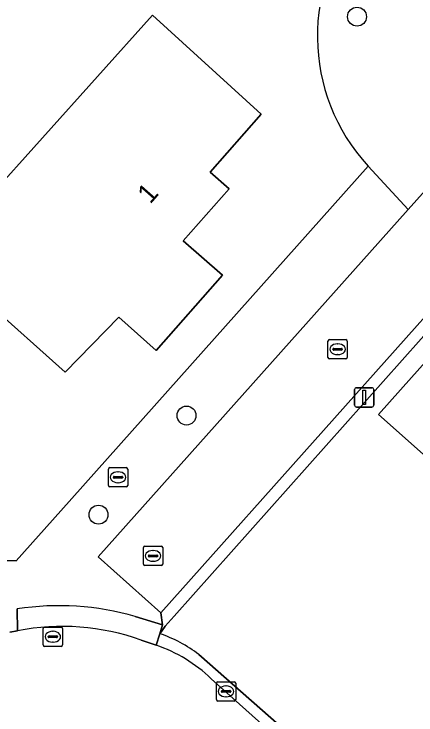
# Model space of a CAD drawing. Extents: x 157648 to 158502, y 379212 to 380938.
# Drawn here: x 158375.88 to 158396.67, y 380278.71 to 380314.96 of the extents above; entities that cross this region are included whole.
import ezdxf

# ---------------------------------------------------------------- set-up
doc = ezdxf.new("R2010")
doc.units = 0
for name, color, linetype in [('IMGEO_Boom', 7, 'Continuous'), ('IMGEO_Brandkraan', 7, 'Continuous'), ('IMGEO_Erf', 7, 'Continuous'), ('IMGEO_Kolk', 7, 'Continuous'), ('IMGEO_Lichtmast', 7, 'Continuous'), ('IMGEO_Pand', 7, 'Continuous'), ('IMGEO_Pand_nummerreeks', 7, 'Continuous'), ('IMGEO_Rijbaan_lokaal_open', 7, 'Continuous'), ('IMGEO_Rioolput', 7, 'Continuous'), ('IMGEO_Voetpad_open', 7, 'Continuous')]:
    doc.layers.add(name, color=color, linetype=linetype)

msp = doc.modelspace()

# ---------------------------------------------------------------- linework, layer by layer
at = {"layer": 'IMGEO_Boom'}
for centre in [(158393.623, 380314.818), (158384.804, 380294.193), (158380.252, 380289.068)]:
    msp.add_circle(centre, 0.489, dxfattribs=at)
at = {"layer": 'IMGEO_Brandkraan'}
for p, q in [((158380.763, 380290.577), (158380.763, 380291.429)), ((158380.838, 380291.503), (158381.69, 380291.503)), ((158381.251, 380291.283), (158381.276, 380291.283)), ((158381.764, 380291.429), (158381.764, 380290.577)), ((158381.022, 380290.997), (158381.022, 380291.009)), ((158381.46, 380290.96), (158381.062, 380290.96)), ((158381.065, 380291.046), (158381.463, 380291.046)), ((158381.506, 380291.009), (158381.506, 380290.997)), ((158381.69, 380290.503), (158380.838, 380290.503)), ((158381.274, 380290.723), (158381.249, 380290.723))]:
    msp.add_line(p, q, dxfattribs=at)
for points in [[(158380.763, 380290.577), (158380.763, 380291.429)], [(158380.838, 380291.503), (158381.69, 380291.503)], [(158381.764, 380291.429), (158381.764, 380290.577)], [(158381.69, 380290.503), (158380.838, 380290.503)]]:
    msp.add_lwpolyline(points, dxfattribs=at)
for centre, radius, start, end in [((158380.84, 380291.427), 0.0765, 91.552, 178.448), ((158380.84, 380291.427), 0.0765, 91.552, 178.448), ((158381.688, 380291.427), 0.0765, 1.552, 88.448), ((158381.688, 380291.427), 0.0765, 1.552, 88.448), ((158381.062, 380291.006), 0.0403, 85.8775, 175.7526), ((158381.059, 380290.996), 0.0366, 178.938, 274.7102), ((158381.463, 380291.003), 0.043, 264.8664, 352.4533), ((158381.467, 380291.008), 0.0386, 1.7309, 96.639), ((158380.84, 380290.579), 0.0765, 181.552, 268.448), ((158380.84, 380290.579), 0.0765, 181.552, 268.448), ((158381.688, 380290.579), 0.0765, 271.552, 358.448), ((158381.688, 380290.579), 0.0765, 271.552, 358.448)]:
    msp.add_arc(centre, radius, start, end, dxfattribs=at)
for centre, major_axis, ratio, start_param, end_param in [((158381.25, 380291.003), (-0.387, 0.002), 0.722429, 4.712389, 7.853982), ((158381.275, 380291.003), (-0.39, 0.002), 0.717154, 1.570796, 4.712389)]:
    msp.add_ellipse(centre, major_axis=major_axis, ratio=ratio, start_param=start_param, end_param=end_param, dxfattribs=at)
at = {"layer": 'IMGEO_Erf'}
for points in [[(158328.87, 380322.271), (158368.445, 380286.775), (158375.993, 380286.676), (158378.309, 380289.272), (158394.201, 380307.087)], [(158401.856, 380303.677), (158384.171, 380283.829), (158383.699, 380283.299), (158383.423, 380282.912)], [(158385.44, 380281.833), (158396.328, 380272.254), (158441.82, 380231.568), (158462.293, 380254.879), (158454.886, 380261.5), (158454.843, 380261.446), (158407.523, 380303.702)]]:
    msp.add_lwpolyline(points, dxfattribs=at)
for points in [[(158388.658, 380309.781), (158386.027, 380306.778), (158387.003, 380305.924), (158384.635, 380303.221), (158386.662, 380301.445), (158383.239, 380297.562), (158381.298, 380299.274), (158378.522, 380296.432), (158374.419, 380300.086), (158371.82, 380302.401), (158374.502, 380305.388), (158383.041, 380314.899)], [(158398.039, 380293.002), (158397.192, 380292.054), (158394.735, 380294.251), (158400.72, 380300.945), (158402.983, 380298.922), (158404.602, 380300.734), (158411.647, 380294.436), (158404.89, 380286.877)]]:
    msp.add_lwpolyline(points, close=True, dxfattribs=at)
for centre, radius, start, end in [((158401.513, 380313.822), 9.941, 138.8215, 222.6454), ((158381.313, 380276.543), 6.709, 52.0401, 71.6706)]:
    msp.add_arc(centre, radius, start, end, dxfattribs=at)
at = {"layer": 'IMGEO_Kolk'}
for p, q in [((158392.194, 380298.122), (158393.046, 380298.122)), ((158392.119, 380297.196), (158392.119, 380298.048)), ((158392.607, 380297.902), (158392.632, 380297.902)), ((158393.12, 380298.048), (158393.12, 380297.196)), ((158392.378, 380297.616), (158392.378, 380297.628)), ((158392.816, 380297.579), (158392.418, 380297.579)), ((158392.421, 380297.665), (158392.819, 380297.665)), ((158392.862, 380297.628), (158392.862, 380297.616)), ((158393.046, 380297.122), (158392.194, 380297.122)), ((158392.63, 380297.342), (158392.605, 380297.342)), ((158382.572, 380286.511), (158382.572, 380287.363)), ((158382.647, 380287.437), (158383.499, 380287.437)), ((158383.06, 380287.217), (158383.085, 380287.217)), ((158383.573, 380287.363), (158383.573, 380286.511)), ((158382.831, 380286.931), (158382.831, 380286.943)), ((158383.269, 380286.894), (158382.871, 380286.894)), ((158382.874, 380286.98), (158383.272, 380286.98)), ((158383.315, 380286.943), (158383.315, 380286.931)), ((158383.083, 380286.657), (158383.058, 380286.657)), ((158383.499, 380286.437), (158382.647, 380286.437)), ((158386.347, 380279.506), (158386.347, 380280.358)), ((158386.422, 380280.432), (158387.274, 380280.432)), ((158387.348, 380280.358), (158387.348, 380279.506)), ((158386.649, 380279.975), (158387.047, 380279.975)), ((158386.835, 380280.212), (158386.86, 380280.212)), ((158386.606, 380279.926), (158386.606, 380279.938)), ((158387.044, 380279.889), (158386.646, 380279.889)), ((158386.858, 380279.652), (158386.833, 380279.652)), ((158387.09, 380279.938), (158387.09, 380279.926)), ((158387.274, 380279.432), (158386.422, 380279.432))]:
    msp.add_line(p, q, dxfattribs=at)
for points in [[(158392.194, 380298.122), (158393.046, 380298.122)], [(158392.119, 380297.196), (158392.119, 380298.048)], [(158393.12, 380298.048), (158393.12, 380297.196)], [(158393.046, 380297.122), (158392.194, 380297.122)], [(158382.572, 380286.511), (158382.572, 380287.363)], [(158382.647, 380287.437), (158383.499, 380287.437)], [(158383.573, 380287.363), (158383.573, 380286.511)], [(158383.499, 380286.437), (158382.647, 380286.437)], [(158386.347, 380279.506), (158386.347, 380280.358)], [(158386.422, 380280.432), (158387.274, 380280.432)], [(158387.348, 380280.358), (158387.348, 380279.506)], [(158387.274, 380279.432), (158386.422, 380279.432)]]:
    msp.add_lwpolyline(points, dxfattribs=at)
for centre, radius, start, end in [((158392.196, 380298.046), 0.0765, 91.552, 178.448), ((158392.196, 380298.046), 0.0765, 91.552, 178.448), ((158393.044, 380298.046), 0.0765, 1.552, 88.448), ((158393.044, 380298.046), 0.0765, 1.552, 88.448), ((158392.418, 380297.625), 0.0403, 85.8775, 175.7526), ((158392.415, 380297.615), 0.0366, 178.938, 274.7102), ((158392.819, 380297.622), 0.043, 264.8664, 352.4533), ((158392.823, 380297.627), 0.0386, 1.7309, 96.639), ((158392.196, 380297.198), 0.0765, 181.552, 268.448), ((158392.196, 380297.198), 0.0765, 181.552, 268.448), ((158393.044, 380297.198), 0.0765, 271.552, 358.448), ((158393.044, 380297.198), 0.0765, 271.552, 358.448), ((158382.649, 380287.361), 0.0765, 91.552, 178.448), ((158382.649, 380287.361), 0.0765, 91.552, 178.448), ((158383.497, 380287.361), 0.0765, 1.552, 88.448), ((158383.497, 380287.361), 0.0765, 1.552, 88.448), ((158382.871, 380286.94), 0.0403, 85.8775, 175.7526), ((158382.868, 380286.93), 0.0366, 178.938, 274.7102), ((158383.272, 380286.937), 0.043, 264.8664, 352.4533), ((158383.276, 380286.942), 0.0386, 1.7309, 96.639), ((158382.649, 380286.513), 0.0765, 181.552, 268.448), ((158382.649, 380286.513), 0.0765, 181.552, 268.448), ((158383.497, 380286.513), 0.0765, 271.552, 358.448), ((158383.497, 380286.513), 0.0765, 271.552, 358.448), ((158386.424, 380280.356), 0.0765, 91.552, 178.448), ((158386.424, 380280.356), 0.0765, 91.552, 178.448), ((158387.272, 380280.356), 0.0765, 1.552, 88.448), ((158387.272, 380280.356), 0.0765, 1.552, 88.448), ((158386.646, 380279.935), 0.0403, 85.8775, 175.7526), ((158387.051, 380279.937), 0.0386, 1.7309, 96.639), ((158386.643, 380279.925), 0.0366, 178.938, 274.7102), ((158387.047, 380279.932), 0.043, 264.8664, 352.4533), ((158386.424, 380279.508), 0.0765, 181.552, 268.448), ((158386.424, 380279.508), 0.0765, 181.552, 268.448), ((158387.272, 380279.508), 0.0765, 271.552, 358.448), ((158387.272, 380279.508), 0.0765, 271.552, 358.448)]:
    msp.add_arc(centre, radius, start, end, dxfattribs=at)
for centre, major_axis, ratio, start_param, end_param in [((158392.606, 380297.622), (-0.387, 0.002), 0.722429, 4.712389, 7.853982), ((158392.631, 380297.622), (-0.39, 0.002), 0.717154, 1.570796, 4.712389), ((158383.059, 380286.937), (-0.387, 0.002), 0.722429, 4.712389, 7.853982), ((158383.084, 380286.937), (-0.39, 0.002), 0.717154, 1.570796, 4.712389), ((158386.834, 380279.932), (-0.387, 0.002), 0.722429, 4.712389, 7.853982), ((158386.859, 380279.932), (-0.39, 0.002), 0.717154, 1.570796, 4.712389)]:
    msp.add_ellipse(centre, major_axis=major_axis, ratio=ratio, start_param=start_param, end_param=end_param, dxfattribs=at)
at = {"layer": 'IMGEO_Lichtmast'}
for p, q in [((158393.599, 380295.633), (158394.389, 380295.633)), ((158394.389, 380295.633), (158393.599, 380295.633)), ((158393.499, 380294.733), (158393.499, 380295.533)), ((158393.499, 380295.533), (158393.499, 380294.733)), ((158394.489, 380295.533), (158394.489, 380294.733)), ((158394.489, 380294.733), (158394.489, 380295.533)), ((158394.389, 380294.633), (158393.599, 380294.633)), ((158393.599, 380294.633), (158394.389, 380294.633))]:
    msp.add_line(p, q, dxfattribs=at)
msp.add_lwpolyline([(158393.919, 380295.508), (158394.069, 380295.508), (158394.069, 380294.758), (158393.919, 380294.758), (158393.919, 380295.508)], dxfattribs=at)
for centre, start, end in [((158393.599, 380295.533), 90, 180), ((158393.599, 380295.533), 90, 180), ((158394.389, 380295.533), 0, 90), ((158394.389, 380295.533), 360, 90), ((158393.599, 380294.733), 180, 270), ((158393.599, 380294.733), 180, 270), ((158394.389, 380294.733), 270, 0), ((158394.389, 380294.733), 270, 0)]:
    msp.add_arc(centre, 0.1, start, end, dxfattribs=at)
at = {"layer": 'IMGEO_Pand'}
for points in [[(158386.662, 380301.445), (158384.635, 380303.221), (158387.003, 380305.924), (158386.027, 380306.778), (158388.658, 380309.781), (158383.041, 380314.899), (158374.502, 380305.388), (158371.82, 380302.401), (158374.419, 380300.086), (158378.522, 380296.432), (158381.298, 380299.274), (158383.239, 380297.562)], [(158404.89, 380286.877), (158411.647, 380294.436), (158404.602, 380300.734), (158402.983, 380298.922), (158400.72, 380300.945), (158394.735, 380294.251), (158397.192, 380292.054), (158398.039, 380293.002)]]:
    msp.add_lwpolyline(points, close=True, dxfattribs=at)
at = {"layer": 'IMGEO_Rijbaan_lokaal_open'}
for points in [[(158398.936, 380307.825), (158396.269, 380304.841), (158380.229, 380286.895), (158383.483, 380283.998), (158401.435, 380304.124)], [(158376.064, 380283.067), (158375.664, 380282.997)], [(158383.233, 380282.319), (158382.454, 380282.582)], [(158446.344, 380226.702), (158444.879, 380228.012), (158386.082, 380280.588)]]:
    msp.add_lwpolyline(points, dxfattribs=at)
for centre, radius, start, end in [((158378.382, 380271.267), 12.025, 70.2058, 101.1133), ((158380.691, 380274.925), 7.819, 46.409, 71.0268)]:
    msp.add_arc(centre, radius, start, end, dxfattribs=at)
at = {"layer": 'IMGEO_Rioolput'}
for p, q in [((158377.467, 380283.259), (158378.319, 380283.259)), ((158377.392, 380282.333), (158377.392, 380283.185)), ((158377.88, 380283.039), (158377.905, 380283.039)), ((158378.393, 380283.185), (158378.393, 380282.333)), ((158377.651, 380282.753), (158377.651, 380282.765)), ((158378.089, 380282.716), (158377.691, 380282.716)), ((158377.694, 380282.802), (158378.092, 380282.802)), ((158378.135, 380282.765), (158378.135, 380282.753)), ((158378.319, 380282.259), (158377.467, 380282.259)), ((158377.903, 380282.479), (158377.878, 380282.479))]:
    msp.add_line(p, q, dxfattribs=at)
for points in [[(158377.467, 380283.259), (158378.319, 380283.259)], [(158377.392, 380282.333), (158377.392, 380283.185)], [(158378.393, 380283.185), (158378.393, 380282.333)], [(158378.319, 380282.259), (158377.467, 380282.259)]]:
    msp.add_lwpolyline(points, dxfattribs=at)
for centre, radius, start, end in [((158377.469, 380283.183), 0.0765, 91.552, 178.448), ((158377.469, 380283.183), 0.0765, 91.552, 178.448), ((158378.317, 380283.183), 0.0765, 1.552, 88.448), ((158378.317, 380283.183), 0.0765, 1.552, 88.448), ((158377.691, 380282.762), 0.0403, 85.8775, 175.7526), ((158377.688, 380282.752), 0.0366, 178.938, 274.7102), ((158378.092, 380282.759), 0.043, 264.8664, 352.4533), ((158378.096, 380282.764), 0.0386, 1.7309, 96.639), ((158377.469, 380282.335), 0.0765, 181.552, 268.448), ((158377.469, 380282.335), 0.0765, 181.552, 268.448), ((158378.317, 380282.335), 0.0765, 271.552, 358.448), ((158378.317, 380282.335), 0.0765, 271.552, 358.448)]:
    msp.add_arc(centre, radius, start, end, dxfattribs=at)
for centre, major_axis, ratio, start_param, end_param in [((158377.879, 380282.759), (-0.387, 0.002), 0.722429, 4.712389, 7.853982), ((158377.904, 380282.759), (-0.39, 0.002), 0.717154, 1.570796, 4.712389)]:
    msp.add_ellipse(centre, major_axis=major_axis, ratio=ratio, start_param=start_param, end_param=end_param, dxfattribs=at)
at = {"layer": 'IMGEO_Voetpad_open'}
for points in [[(158394.201, 380307.087), (158396.269, 380304.841), (158398.936, 380307.825)], [(158396.269, 380304.841), (158394.201, 380307.087), (158378.309, 380289.272), (158375.993, 380286.676), (158368.445, 380286.775), (158368.046, 380286.323), (158369.829, 380284.728)], [(158382.153, 380283.803), (158383.568, 380283.368), (158383.483, 380283.998), (158380.229, 380286.895), (158396.269, 380304.841)], [(158401.435, 380304.124), (158383.483, 380283.998), (158383.568, 380283.368), (158383.423, 380282.912), (158383.699, 380283.299), (158384.171, 380283.829), (158401.856, 380303.677)], [(158375.664, 380282.997), (158376.064, 380283.067), (158376.05, 380284.195)], [(158376.05, 380284.195), (158376.064, 380283.067)], [(158382.454, 380282.582), (158383.233, 380282.319), (158383.423, 380282.912), (158383.568, 380283.368), (158382.153, 380283.803)], [(158383.423, 380282.912), (158383.233, 380282.319)], [(158386.082, 380280.588), (158444.879, 380228.012), (158445.173, 380228.353), (158445.278, 380228.475), (158444.13, 380229.501), (158441.82, 380231.568), (158396.328, 380272.254), (158385.44, 380281.833)]]:
    msp.add_lwpolyline(points, dxfattribs=at)
for centre, radius, start, end in [((158401.513, 380313.822), 9.941, 138.8215, 222.6454), ((158378.222, 380270.31), 14.054, 73.7581, 98.8917), ((158378.222, 380270.31), 14.054, 73.7581, 98.8917), ((158378.382, 380271.267), 12.025, 70.2058, 101.1133), ((158381.313, 380276.543), 6.709, 52.0401, 71.6706), ((158380.691, 380274.925), 7.819, 46.409, 71.0268)]:
    msp.add_arc(centre, radius, start, end, dxfattribs=at)

# ---------------------------------------------------------------- texts
at = {"layer": 'IMGEO_Pand_nummerreeks'}
msp.add_text('1', height=1, rotation=48.7816, dxfattribs=at).set_placement((158382.926, 380305.095))

doc.saveas('drawing.dxf')
